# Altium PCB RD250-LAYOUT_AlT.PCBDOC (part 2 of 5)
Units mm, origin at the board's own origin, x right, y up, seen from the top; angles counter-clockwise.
Board outline 318.5 x 135 mm, 6 copper layers (TOP, Mid-Layer 1, Mid-Layer 2, Mid-Layer 3, Mid-Layer 4, BOTTOM), stack 1.422 mm thick; 550 components, 251 nets, 1350 pads, 626 vias.
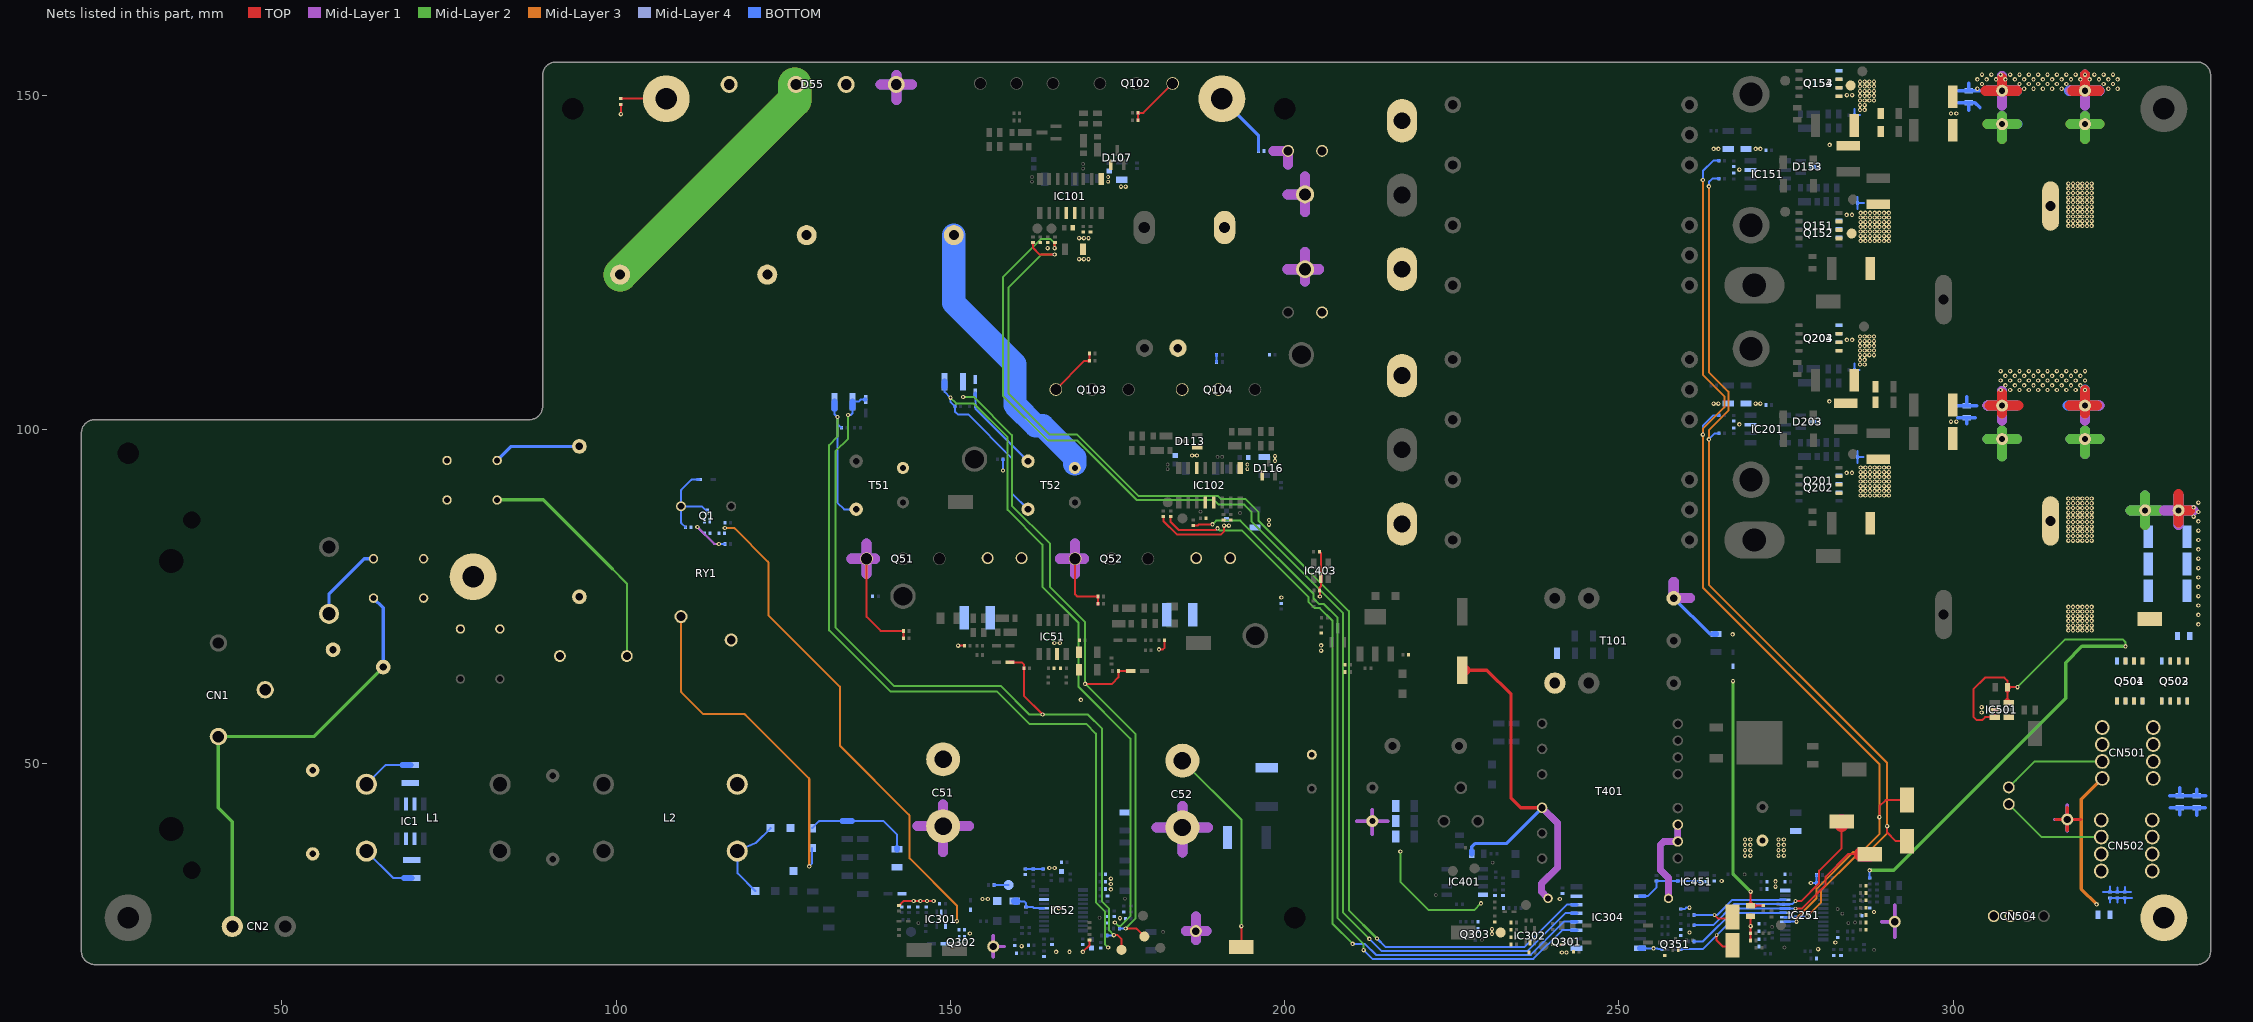
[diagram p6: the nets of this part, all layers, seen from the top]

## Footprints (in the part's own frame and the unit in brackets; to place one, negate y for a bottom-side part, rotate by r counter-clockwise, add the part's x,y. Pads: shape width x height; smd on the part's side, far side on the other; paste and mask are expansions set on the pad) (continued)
Local_TAM0545 [mm] "KC00080BKP"
  round 2.5 hole 1.4 paste-2.5 mask+0: 1(-13.5,-17.7) 3(-4.5,-17.7) 4(4.5,-17.7) 6(13.5,-17.7) 7(13.5,17.7) 8(9,17.7) 9(4.5,17.7) 10(-4.5,17.7) 11(-9,17.7) 12(-13.5,17.7)
  silkscreen extent -18.7,-20.7 18.7,20.7
Local_TAM-PQ20-36-5 [mil] "KC00080BKP"
  round 62 / inner round 52 / far side round 62 hole 42 paste-62 mask+0: 1(-397.64,-399.61) 2(-248.03,-399.61) 3(-98.43,-399.61) 4(98.43,-399.61) 5(248.03,-399.61) 6(397.64,-399.61) 7(395.28,399.61) 8(296.85,399.61) 9(198.43,399.61) 10(100,399.61) 11(-100,399.61) 12(-198.43,399.61) 13(-296.85,399.61) 14(-395.28,399.61)
  silkscreen extent -500,-539 500,539
Local_TH350-P550 [mm] "KC00080BKP"
  round 5.5 hole 3.5 paste-5.5 mask+0: 1(0,0)
  silkscreen extent -3,-3 3,3
Local_TMSD-Y3001 [mm] "KC00080BKP"
  oval 5x3.2 / inner round 0 / far side oval 5x3.2 hole 1.7 slot 3.5 at 0 deg paste-5 mask+0: 1(0,-6) 2(0,6)
Local_TO-220-2L-A [mil] "KC00080BKP"
  round 70 / inner round 0 / far side round 70 hole 51.18 paste-70 mask+0: A(0,0) C(200,0)
  silkscreen extent -109,-121 309,72
Local_TO-220SIS-02-A [mm] "KC00080BKP"
  round 1.9 hole 1.3 paste-2 mask+0: D(0,-5) G(-2.54,0) S(2.54,0)
  silkscreen extent -5,-3.84 5,2.92
Local_Y5JA-330JPTL3_5-A [mm] "KC00080BKP"
  round 1.778 / inner round 0 / far side round 1.778 hole 1.2 paste-1.778 mask+0: 1(-5,0) 2(5,0)
  silkscreen extent -9.7,-5.35 9.7,5.35
LocalI9K0A8 [mm] "KC00080BKP"
  rect 0.825x1.795 smd paste-1.795 mask+0: 1(-4.583,-4.72) 8(4.583,-4.72) 9(4.583,4.72) 16(-4.583,4.72)
  rect 0.55x1.795 smd paste-1.795 mask+0: 2(-3.175,-4.72) 3(-1.905,-4.72) 4(-0.635,-4.72) 5(0.635,-4.72) 6(1.905,-4.72) 7(3.175,-4.72) 10(3.175,4.72) 11(1.905,4.72) 12(0.635,4.72) 13(-0.635,4.72) 14(-1.905,4.72) 15(-3.175,4.72)
  silkscreen extent -5.3,-5.92 5.25,3.32
MM00340AKP [mm] "KC00080BKP"
  rect 0.5x0.9 smd paste-0.9 mask+0: D(0,0.65)
  rect 0.4x0.9 smd paste-0.9 mask+0: G(-0.4,-0.65) S(0.4,-0.65)
  silkscreen extent -0.65,0.1 0.65,0.45
MM00340BKP [mm] "KC00080BKP"
  rect 0.5x0.9 smd paste-0.9 mask+0: D(0,-0.65)
  rect 0.4x0.9 smd paste-0.9 mask+0: G(0.4,0.65) S(-0.4,0.65)
  silkscreen extent -0.65,-0.45 0.65,-0.1
MM00730AKP [mm] "KC00080BKP"
  rect 0.4x0.95 smd paste-0.95 mask+0: 1(-0.65,-0.975) 2(0,-0.975) 3(0.65,-0.975) 4(0.65,0.975) 5(-0.65,0.975)
MM00730BKP [mm] "KC00080BKP"
  rect 0.4x0.95 smd paste-0.95 mask+0: 1(-0.65,-0.975) 2(0,-0.975) 3(0.65,-0.975) 4(0.65,0.975) 5(-0.65,0.975)
MM01320AKP [mm] "KC00080BKP"
  rect 1x2.25 smd paste-2.25 mask+0: 1(-2.3,-2.775) 2(0,-2.775) 3(2.3,-2.775)
  rect 3.2x2.25 smd paste-3.2 mask+0: 4(0,2.775)
  silkscreen extent -3.35,-1.85 3.35,1.85
MMK01670AKP [mm] "KC00080BKP"
  rect 1.212x1.2 smd paste-1.212 mask+0: A(-1.494,0) C(1.494,0)
  silkscreen extent -2.4,-0.9 2.9,0.9
MMK01670BKP [mm] "KC00080BKP"
  rect 1.212x1.2 smd paste-1.212 mask+0: A(1.494,0) C(-1.494,0)
  silkscreen extent -2.9,-0.9 2.4,0.9
NTC320 [mm] "KC00080BKP"
  round 0 hole 3.2 unplated paste-3.5 mask+0: ""(0,0)
R8100A [mm] "KC00080BKP"
  rect 1.405x3.4 smd paste-3.4 mask+0: 1(-2.903,0) 2(2.902,0)
R9100A [mm] "KC00080BKP"
  rect 1.405x3.4 smd paste-3.4 mask+0: 1(-2.903,0) 2(2.902,0)
RDP10020ATP#1 [mm] "KC00080BKP"
  round 1.9 / inner round 0 / far side round 1.9 hole 1.65 paste-1.9 mask+0: D(5.44,0) G(0,0) S(10.88,0)
  silkscreen extent -3.15,-2.9 14.05,3.35
RDP10020ATP#2 [mm] "KC00080BKP"
  round 1.9 / inner round 0 / far side round 1.9 hole 1.65 paste-1.9 mask+0: D(5.44,0) G(0,0)
  round 1.9 / inner round 2 / far side round 1.9 hole 1.65 paste-1.9 mask+0: S(10.88,0)
  silkscreen extent -3.15,-2.9 14.05,3.35
SIK00180ATP_RD244-A [mm] "KC00080BKP"
  round 1.4 / inner round 0 / far side round 1.4 hole 0.9 paste-1.4 mask+0: 1(-5.25,0) 2(12.75,0)
  silkscreen extent -4.8,-3 12.3,3
SOT-23-6_KA [mm] "KC00080BKP"
  rect 0.825x1.56 smd paste-1.56 mask+0: 1(-1.087,-1.075) 3(1.088,-1.075) 4(1.088,1.075) 6(-1.087,1.075)
  rect 0.55x1.56 smd paste-1.56 mask+0: 2(0,-1.075) 5(0,1.075)
T3.2_7.0 [mm] "KC00080BKP"
  round 7 / inner round 0 / far side round 7 hole 3.2 paste-7.1 mask+0: ""(0,0)
US2H_A [mm] "KC00080BKP"
  rect 0.8x1.1 smd paste-1.1 mask+0: A(1.25,0)
  rect 2x1.1 smd paste-2 mask+0: C(-0.65,0)
  silkscreen extent -1.9,-0.9 1.9,0.9
US2H_B [mm] "KC00080BKP"
  rect 0.8x1.1 smd paste-1.1 mask+0: A(-1.25,0)
  rect 2x1.1 smd paste-2 mask+0: C(0.65,0)
  silkscreen extent -1.95,-0.85 2.01,0.85
UTOS12 [mm] "KC00080BKP"

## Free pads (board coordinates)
  round 0.55 / inner round 0 / far side round 0.55 hole 0.3 paste-0.55 mask+0: ""(145.2,26.2) ""(162.2,137.1) ""(162.2,137.8) ""(169.85,139.05) ""(169.85,139.75) ""(172.3,27) ""(173.6,137.1) ""(173.6,137.8) ""(176.1,29.85) ""(181.8,24.9) ""(182.5,94.1) ""(182.5,94.8) ""(187.4,87.75) ""(189.95,95.95) ""(190.65,95.95) ""(193.3,87.55) ""(194.4,94.1) ""(194.4,94.8) ""(222.6,30.4) ""(229.5,23.7) ""(231.1,35.25) ""(264.3,27.4) ""(264.6,24.4) ""(268.8,33.5) ""(272.9,25.65) ""(274.75,22.55) ""(276.4,28.35) ""(276.4,29.5) ""(282.7,28.3) ""(283.4,27.6) ""(284.3,26.2) ""(285.3,26.3) ""(288.15,22.2)
  round 0 hole 1 slot 13.5 at 0 deg unplated paste-13.5 mask+0: ""(168,134.95) ""(188.8,91.7)

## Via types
v1: diameter 0.65, hole 0.3, TOP to BOTTOM, 626 vias

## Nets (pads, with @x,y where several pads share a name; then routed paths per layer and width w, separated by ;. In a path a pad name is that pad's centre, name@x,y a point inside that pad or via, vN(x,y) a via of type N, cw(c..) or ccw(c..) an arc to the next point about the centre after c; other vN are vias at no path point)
ACIN: C301.2 D51.C D52.C R301.1 | length 16.2
  BOTTOM w0.3: D51.C@129.3,40.394 130.324,41.418 cw(c130.466,41.277) 130.466,41.477 R301.1@133.888,41.477 ; R301.1@135.278,41.477 139.897,41.477 cw(c139.897,41.277) 140.038,41.419 141.941,39.516 cw(c141.8,39.374) 142,39.374 C301.2@142,37.433
  BOTTOM w0.92: R301.1@133.888,41.477 R301.1@134.583,41.477 R301.1@135.278,41.477 ; C301.2@142,37.25 C301.2@142,37.433
CONN002: C119.1 C120.1 CN101.1 CN104.1 D113.A IC102.14 Q103.S Q104.D R121.1 | length 7.9
  TOP w0.3: Q103.S@165.72,106 170.02,110.3 C120.1@170.597,110.3 ; C120.1@170.775,110.478 R121.1@170.775,111.222
  TOP w0.45: C120.1@170.597,110.3 C120.1@170.775,110.3 C120.1@170.775,110.478 ; R121.1@170.775,111.222 R121.1@170.775,111.4
  other v1: 186.15,96.15 186.85,96.15
CONN003: CN103.1 CN106.1 D108.A D109.C L101.2
CONN004: C501.2 C502.2 C503.2 C504.2 C505.2 C506.2 C507.2 C508.2 C509.2 DP503.1 IC501.3 IC501.6 L151.F L201.F Q501.1 Q501.2 Q501.3 Q502.1 Q502.2 Q502.3 Q503.1 Q503.2 Q503.3 Q504.1 Q504.2 Q504.3 R162.2 R163.2 R212.2 R213.2 R287.2 R501.2 R502.2 R503.2 | length 222.9
  TOP w0.3: IC501.3@305.808,57.012 304.762,57.012 304.3,56.55 303.5,56.55 303,57.05 303,61.15 304.75,62.9 307.65,62.9 308.1,62.45 C509.2@308.1,61.81 ; IC501.6@308.1,59.469 C509.2@308.1,61.031 ; C509.2@308.21,61.5 v1(309.6,61.5)
  TOP w0.8: C509.2@308.1,61.031 C509.2@308.1,61.5 ; C509.2@308.1,61.81 C509.2@308.1,61.5 ; C509.2@308.21,61.5 C509.2@308.1,61.5
  TOP w0.825: IC501.3@305.808,57.012 IC501.3@306.175,57.012 ; IC501.6@308.1,59.187 IC501.6@308.1,59.469
  Mid-Layer 2 w0.3: v1(309.6,61.5) 316.75,68.65 325.35,68.65 325.75,68.25 v1(325.75,67.6)
  Mid-Layer 2 w0.5: v1(287.5,34.1) 291.1,34.1 316.8,59.8 316.8,65.15 319.25,67.6 v1(325.75,67.6)
  Mid-Layer 2 w1.5: 305.1,98.6 C504.2@307.3,98.6 ; 305.1,145.7 C501.2@307.3,145.7 ; 307.3,96 C504.2@307.3,98.6 ; 307.3,99.85 C504.2@307.3,98.6 ; 307.3,143.5 C501.2@307.3,145.7 ; 307.3,146.95 C501.2@307.3,145.7 ; 309.5,98.6 C504.2@307.3,98.6 ; 309.5,145.7 C501.2@307.3,145.7 ; 317.5,98.6 C505.2@319.7,98.6 ; 317.5,145.7 C502.2@319.7,145.7 ; 319.7,96.4 C505.2@319.7,98.6 ; 319.7,99.85 C505.2@319.7,98.6 ; 319.7,143.5 C502.2@319.7,145.7 ; 319.7,146.95 C502.2@319.7,145.7 ; 321.9,98.6 C505.2@319.7,98.6 ; 321.9,145.7 C502.2@319.7,145.7 ; 326.5,87.95 C503.2@328.7,87.95 ; 328.7,85.75 C503.2@328.7,87.95 ; 328.7,90.15 C503.2@328.7,87.95 ; 330.9,87.95 C503.2@328.7,87.95
  Mid-Layer 3 w1.5: 305.1,98.6 C504.2@307.3,98.6 ; 305.1,145.7 C501.2@307.3,145.7 ; 307.3,96.05 C504.2@307.3,98.6 ; 307.3,99.85 C504.2@307.3,98.6 ; 307.3,143.5 C501.2@307.3,145.7 ; 307.3,146.95 C501.2@307.3,145.7 ; 309.5,98.6 C504.2@307.3,98.6 ; 309.5,145.7 C501.2@307.3,145.7 ; 317.5,98.6 C505.2@319.7,98.6 ; 317.5,145.7 C502.2@319.7,145.7 ; 319.7,96.4 C505.2@319.7,98.6 ; 319.7,99.85 C505.2@319.7,98.6 ; 319.7,143.5 C502.2@319.7,145.7 ; 319.7,146.95 C502.2@319.7,145.7 ; 321.9,98.6 C505.2@319.7,98.6 ; 321.9,145.7 C502.2@319.7,145.7 ; 326.5,87.95 C503.2@328.7,87.95 ; 328.7,85.75 C503.2@328.7,87.95 ; 328.7,90.15 C503.2@328.7,87.95 ; 330.9,87.95 C503.2@328.7,87.95
  BOTTOM w0.3: R287.2@287.5,33.103 v1(287.5,34.1)
  BOTTOM w0.45: R287.2@287.5,32.925 R287.2@287.5,33.103
  BOTTOM w0.5: 300.65,101.8 C506.2@302,101.8 ; 300.75,148.9 C507.2@302.3,148.9 ; 302,100.9 C506.2@302,101.8 ; 302.3,147.75 C507.2@302.3,148.9 ; 303.3,101.8 C506.2@302,101.8 ; 304,148.15 303.25,148.9 C507.2@302.3,148.9
  BOTTOM w1.5: 305.1,98.6 C504.2@307.3,98.6 ; 305.25,145.7 C501.2@307.3,145.7 ; 307.3,96.05 C504.2@307.3,98.6 ; 307.3,99.85 C504.2@307.3,98.6 ; 307.3,143.65 C501.2@307.3,145.7 ; 307.3,146.95 C501.2@307.3,145.7 ; 309.5,98.6 C504.2@307.3,98.6 ; 309.6,145.7 C501.2@307.3,145.7 ; 317.5,98.6 C505.2@319.7,98.6 ; 317.9,145.7 C502.2@319.7,145.7 ; 319.7,96.4 C505.2@319.7,98.6 ; 319.7,99.8 C505.2@319.7,98.6 ; 319.7,144 C502.2@319.7,145.7 ; 319.7,146.95 C502.2@319.7,145.7 ; 321.7,145.7 C502.2@319.7,145.7 ; 321.9,98.6 C505.2@319.7,98.6 ; 326.5,87.95 C503.2@328.7,87.95 ; 328.7,86.25 C503.2@328.7,87.95 ; 328.7,90.15 C503.2@328.7,87.95 ; 330.9,87.95 C503.2@328.7,87.95
  other v1: 317.2,70 317.9,70 318.6,70 319.3,70 320,70 320.7,70 317.2,70.7 317.9,70.7 318.6,70.7 319.3,70.7 320,70.7 320.7,70.7 317.2,71.4 317.9,71.4 318.6,71.4 319.3,71.4 320,71.4 320.7,71.4 317.2,72.1 317.9,72.1 318.6,72.1 319.3,72.1 320,72.1 320.7,72.1 317.2,72.8 317.9,72.8 318.6,72.8 319.3,72.8 320,72.8 320.7,72.8 317.2,73.5 317.9,73.5 318.6,73.5 319.3,73.5 320,73.5 320.7,73.5 317.2,83.4 317.9,83.4 318.6,83.4 319.3,83.4 320,83.4 320.7,83.4 317.2,84.1 317.9,84.1 318.6,84.1 319.3,84.1 320,84.1 320.7,84.1 317.2,84.8 317.9,84.8 318.6,84.8 319.3,84.8 320,84.8 320.7,84.8 317.2,85.5 317.9,85.5 318.6,85.5 319.3,85.5 320,85.5 320.7,85.5 317.2,86.2 317.9,86.2 318.6,86.2 319.3,86.2 320,86.2 320.7,86.2 317.2,86.9 317.9,86.9 318.6,86.9 319.3,86.9 320,86.9 320.7,86.9 317.2,87.6 317.9,87.6 318.6,87.6 319.3,87.6 320,87.6 320.7,87.6 317.2,88.3 317.9,88.3 318.6,88.3 319.3,88.3 320,88.3 320.7,88.3 317.2,89 317.9,89 318.6,89 319.3,89 320,89 320.7,89 317.2,89.7 317.9,89.7 318.6,89.7 319.3,89.7 320,89.7 320.7,89.7 299.65,101.2 300.45,101.2 317.2,130.5 317.9,130.5 318.6,130.5 319.3,130.5 320,130.5 320.7,130.5 317.2,131.2 317.9,131.2 318.6,131.2 319.3,131.2 320,131.2 320.7,131.2 317.2,131.9 317.9,131.9 318.6,131.9 319.3,131.9 320,131.9 320.7,131.9 317.2,132.6 317.9,132.6 318.6,132.6 319.3,132.6 320,132.6 320.7,132.6 317.2,133.3 317.9,133.3 318.6,133.3 319.3,133.3 320,133.3 320.7,133.3 317.2,134 317.9,134 318.6,134 319.3,134 320,134 320.7,134 317.2,134.7 317.9,134.7 318.6,134.7 319.3,134.7 320,134.7 320.7,134.7 317.2,135.4 317.9,135.4 318.6,135.4 319.3,135.4 320,135.4 320.7,135.4 317.2,136.1 317.9,136.1 318.6,136.1 319.3,136.1 320,136.1 320.7,136.1 317.2,136.8 317.9,136.8 318.6,136.8 319.3,136.8 320,136.8 320.7,136.8 299.65,147.3 300.45,147.3
CS: D251.C R282.2 R284.2 | length 36.6
  TOP w0.3: R284.2@269.7,29.049 v1(269.7,30.9) ; R284.2@270.116,28.8 R282.2@271.425,28.8
  TOP w0.4: R282.2@271.425,28.8 R282.2@271.6,28.8
  TOP w0.83: R284.2@269.7,29.049 R284.2@269.7,28.8 R284.2@270.116,28.8
  Mid-Layer 2 w0.5: v1(267.05,62.4) 267.05,33.55 v1(269.7,30.9)
CSA: D58.C D62.C DP52.1 R52.2 R59.1 R68.1 | length 129.7
  TOP w0.3: D62.C@159.33,65.2 160.675,65.2 160.975,64.9 R59.1@160.975,64.478 ; R59.1@160.975,64.122 160.975,60.225 v1(163.8,57.4) ; v1(174.45,24.4) 175,24.4 175.6,23.8 DP52.1@175.6,22.2
  TOP w0.45: R59.1@160.975,64.122 R59.1@160.975,64.3 R59.1@160.975,64.478
  TOP w0.55: D62.C@158.925,65.2 D62.C@159.33,65.2
  Mid-Layer 2 w0.3: v1(134.7,102.2) 134.7,98.65 132.8,96.75 132.8,70.45 141.55,61.7 157.5,61.7 161.8,57.4 v1(163.8,57.4) 170.55,57.4 172.7,55.25 172.7,29.4 173.75,28.35 173.75,25.1 v1(174.45,24.4)
  BOTTOM w0.3: v1(134.7,102.2) 135.073,102.2 135.373,102.5 R52.2@135.373,103.216 ; R52.2@135.373,104.2 136.3,104.2 136.625,104.525 D58.C@137.113,104.525 ; R68.1@173.577,24.35 v1@174.45,24.35
  BOTTOM w0.45: R68.1@173.425,24.35 R68.1@173.577,24.35
  BOTTOM w0.55: D58.C@137.113,104.525 D58.C@137.31,104.525
  BOTTOM w0.895: R52.2@135.373,103.216 R52.2@135.373,104.2
CSB: D63.C D67.C DP54.1 R60.2 R67.1 R69.1 | length 104.1
  TOP w0.3: v1(170.15,62) 174.175,62 175.125,62.95 R67.1@175.125,63.722 ; R67.1@175.303,63.9 D67.C@176.373,63.9 ; v1(176.2,25.4) 177.717,25.4 cw(c177.717,25.2) 177.859,25.341 DP54.1@179,24.2
  TOP w0.45: R67.1@175.125,63.722 R67.1@175.125,63.9 R67.1@175.303,63.9
  TOP w0.55: D67.C@176.373,63.9 D67.C@176.975,63.9
  Mid-Layer 2 w0.3: v1(151.9,104.9) 153.5,104.9 159.2,99.2 159.2,88.65 164.9,82.95 164.9,76.45 170.15,71.2 v1(170.15,62) 177.7,54.45 177.7,26.9 v1(176.2,25.4)
  BOTTOM w0.3: R69.1@175.378,25.4 v1(176.2,25.4)
  BOTTOM w0.45: R69.1@175.275,25.4 R69.1@175.378,25.4
FG1: C2.1 C3.1 C4.1 C5.1 C7.1 C8.1 cam7. CN1.2
FG2: C512.1 C513.2 cam5. R505.1 R506.1 | length 5.5
  BOTTOM w0.3: 323.45,29.25 C513.2@323.45,29.975 R505.1@324.55,29.975 ; 324.55,29.25 R505.1@324.55,29.967 R505.1@324.55,29.975 ; 325.65,29.2 R506.1@325.65,29.975 ; 326.75,29.975 R506.1@325.65,29.975 ; R505.1@324.55,29.975 R506.1@325.65,29.975
HS1_1: cam8. R422.2 | length 6.9
  TOP w0.3: R422.2@100.878,149.525 cam8.@107.6,149.525
  TOP w0.45: R422.2@100.7,149.525 R422.2@100.878,149.525
HS1_2: cam2. R423.2 | length 10.1
  BOTTOM w0.5: cam2.@190.6,149.5 196.075,144.025 R423.2@196.075,141.7
LGND: C151.1 C152.1 C153.1 C156.1 C157.1 C158.1 C159.1 C201.1 C202.1 C203.1 C206.1 C207.1 C208.1 C209.1 C251.1 C252.1 C253.1 C254.1 C255.1 C351.1 C414.2 C451.1 C452.1 C453.1 C501.1 C502.1 C503.1 C504.1 C505.1 C506.1 C507.1 C508.1 C510.1 C511.1 C513.1 CN502.1 CN502.2 CN502.3 CN502.4 CN502.5 CN502.6 CN502.7 CN502.8 CN503.2 CN504.3 CN504.4 D153.C D203.C DP153.1 DP156.1 DP257.1 DP501.1 IC151.3 IC201.3 IC251.24 IC304.2 IC304.8 IC451.2 IC501.2 Q151.1 Q151.2 Q151.3 Q152.1 Q152.2 Q152.3 Q153.1 Q153.2 Q153.3 Q154.1 Q154.2 Q154.3 Q201.1 Q201.2 Q201.3 Q202.1 Q202.2 Q202.3 Q203.1 Q203.2 Q203.3 Q204.1 Q204.2 Q204.3 Q351.S R154.1 R155.1 R158.1 R159.1 R160.1 R161.1 R204.1 R205.1 R208.1 R209.1 R210.1 R211.1 R251.1 R252.1 R253.1 R254.1 R255.1 R256.1 R257.1 R258.1 R259.1 R262.1 R264.1 R267.1 R269.1 R271.1 R273.1 R275.1 R276.1 R281.1 R283.1 R284.1 R285.1 R291.1 R352.1 R356.1 R359.1 R362.1 R365.1 R451.1 R501.1 R502.1 R503.1 R505.2 R506.2 T101.3 T401.8 T401.9 | length 311.2
  TOP w0.3: R275.1@269.7,23.769 R271.1@269.7,24.531 ; R271.1@269.7,24.869 v1(269.7,25.75) R284.1@269.7,27.139
  TOP w0.4: R275.1@269.7,23.6 R275.1@269.7,23.769 ; R271.1@269.7,24.531 R271.1@269.7,24.869
  TOP w0.5: 315.3,41.7 DP501.1@317.05,41.7 ; 317.05,40.1 DP501.1@317.05,41.7 ; 317.05,43.45 DP501.1@317.05,41.7 ; 319.05,41.7 DP501.1@317.05,41.7
  TOP w0.83: R284.1@269.7,27.139 R284.1@269.7,27.2
  TOP w1.5: 304.85,150.7 C501.1@307.3,150.7 ; 305.45,103.6 C504.1@307.3,103.6 ; 307.3,102.45 C504.1@307.3,103.6 ; 307.3,105.4 C504.1@307.3,103.6 ; 307.3,152.6 C501.1@307.3,150.7 ; 309.55,150.7 C501.1@307.3,150.7 ; 309.75,103.6 C504.1@307.3,103.6 ; 317.35,103.6 C505.1@319.7,103.6 ; 317.85,150.7 C502.1@319.7,150.7 ; 319.7,102.45 C505.1@319.7,103.6 ; v1(319.7,105.95) C505.1@319.7,103.6 ; v1(319.7,153.1) C502.1@319.7,150.7 ; 321.5,103.6 C505.1@319.7,103.6 ; 321.8,150.7 C502.1@319.7,150.7 ; 333.7,86.1 C503.1@333.7,87.95 ; 333.7,90.35 C503.1@333.7,87.95 ; 335.4,87.95 C503.1@333.7,87.95
  Mid-Layer 1 w0.5: 289.3,26.4 DP257.1@291.25,26.4 ; 291.25,24.05 DP257.1@291.25,26.4 ; 291.25,28.85 DP257.1@291.25,26.4 ; 315.15,41.7 DP501.1@317.05,41.7 ; 317.05,40 DP501.1@317.05,41.7 ; 317.05,43.85 DP501.1@317.05,41.7 ; 318.9,41.7 DP501.1@317.05,41.7
  Mid-Layer 1 w1: C414.2@257.4,29.9 257.4,32.95 256.15,34.2 256.15,37.85 256.71,38.41 T401.8@258.8,38.41 T401.9@258.8,40.91
  Mid-Layer 1 w1.5: 258.19,77.2 T101.3@258.19,74.8 260.59,74.8 ; 305.1,103.6 C504.1@307.3,103.6 ; 305.1,150.7 C501.1@307.3,150.7 ; 307.3,101.4 C504.1@307.3,103.6 ; v1@307.3,105.8 C504.1@307.3,103.6 ; 307.3,148.5 C501.1@307.3,150.7 ; v1@307.3,152.9 C501.1@307.3,150.7 ; 309.5,103.6 C504.1@307.3,103.6 ; 309.5,150.7 C501.1@307.3,150.7 ; 317.5,103.6 C505.1@319.7,103.6 ; 317.5,150.7 C502.1@319.7,150.7 ; 319.7,101.4 C505.1@319.7,103.6 ; v1@319.7,105.8 C505.1@319.7,103.6 ; 319.7,148.5 C502.1@319.7,150.7 ; v1@319.7,152.9 C502.1@319.7,150.7 ; 321.9,103.6 C505.1@319.7,103.6 ; 321.9,150.7 C502.1@319.7,150.7 ; 331.5,87.95 C503.1@333.7,87.95 ; 333.7,85.75 C503.1@333.7,87.95 ; 333.7,90.15 C503.1@333.7,87.95 ; 335.9,87.95 C503.1@333.7,87.95
  Mid-Layer 2 w0.3: CN503.2@308.3,44 313.23,39.07 CN502.2@322.14,39.07
  Mid-Layer 4 w0.5: 289.3,26.4 DP257.1@291.25,26.4 ; 291.25,24.05 DP257.1@291.25,26.4 ; 291.25,28.85 DP257.1@291.25,26.4 ; 315.15,41.7 DP501.1@317.05,41.7 ; 317.05,40 DP501.1@317.05,41.7 ; 317.05,43.85 DP501.1@317.05,41.7 ; 318.9,41.7 DP501.1@317.05,41.7
  Mid-Layer 4 w1: C414.2@257.4,29.9 257.4,32.95 256.15,34.2 256.15,37.85 256.71,38.41 T401.8@258.8,38.41 T401.9@258.8,40.91
  Mid-Layer 4 w1.5: 258.19,77.2 T101.3@258.19,74.8 260.59,74.8 ; 305.1,103.6 C504.1@307.3,103.6 ; 305.1,150.7 C501.1@307.3,150.7 ; 307.3,101.4 C504.1@307.3,103.6 ; v1@307.3,105.8 C504.1@307.3,103.6 ; 307.3,148.5 C501.1@307.3,150.7 ; v1@307.3,152.9 C501.1@307.3,150.7 ; 309.5,103.6 C504.1@307.3,103.6 ; 309.5,150.7 C501.1@307.3,150.7 ; 317.5,103.6 C505.1@319.7,103.6 ; 317.5,150.7 C502.1@319.7,150.7 ; 319.7,101.4 C505.1@319.7,103.6 ; v1@319.7,105.8 C505.1@319.7,103.6 ; 319.7,148.5 C502.1@319.7,150.7 ; v1@319.7,152.9 C502.1@319.7,150.7 ; 321.9,103.6 C505.1@319.7,103.6 ; 321.9,150.7 C502.1@319.7,150.7 ; 331.5,87.95 C503.1@333.7,87.95 ; 333.7,85.75 C503.1@333.7,87.95 ; 333.7,90.15 C503.1@333.7,87.95 ; 335.9,87.95 C503.1@333.7,87.95
  BOTTOM w0.3: IC304.8@253.718,22.417 v1(255.15,22.417) 255.733,22.417 255.85,22.3 R365.1@256.272,22.3 ; IC304.2@253.885,30.225 254.325,30.225 255.6,31.5 C351.1@255.6,32.347 ; C351.1@255.778,32.475 C453.1@258.622,32.475 ; C453.1@258.978,32.475 IC451.2@261.926,32.475 ; R356.1@259.29,28.325 259.875,28.325 260.05,28.5 v1(260.55,28.5) ; v1(278.7,32.2) C254.1@279.5,32.2 ; C254.1@279.575,32.378 R273.1@279.575,33.222 ; 285.225,107.9 R208.1@285.225,108.95 ; 285.225,109.9 R208.1@285.225,108.95 ; 285.225,146.05 R158.1@285.225,147.05 ; 285.225,148 R158.1@285.225,147.05 ; 285.675,95 R204.1@285.675,95.9 ; 285.675,96.85 R204.1@285.675,95.9 ; 285.675,133.05 R154.1@285.675,133.9 ; 285.675,134.8 R154.1@285.675,133.9 ; 286,108.95 R208.1@285.225,108.95 ; 286.05,147.05 R158.1@285.225,147.05 ; 286.55,95.9 R204.1@285.675,95.9 ; 286.65,133.9 R154.1@285.675,133.9 ; 322.4,30.825 C513.1@323.45,30.825 ; 323.45,31.65 C513.1@323.45,30.825 ; 324.55,31.55 R505.2@324.55,30.825 ; 325.65,31.6 R506.2@325.65,30.825 ; 326.6,30.825 R506.2@325.65,30.825 ; C513.1@323.45,30.825 R505.2@324.55,30.825 ; R505.2@324.55,30.825 R506.2@325.65,30.825
  BOTTOM w0.4: IC451.2@261.926,32.475 IC451.2@262.675,32.475
  BOTTOM w0.45: C351.1@255.6,32.347 C351.1@255.6,32.475 C351.1@255.778,32.475 ; R365.1@256.272,22.3 R365.1@256.45,22.3 ; C453.1@258.622,32.475 C453.1@258.8,32.475 C453.1@258.978,32.475 ; R356.1@259.25,28.325 R356.1@259.29,28.325 ; C254.1@279.5,32.2 C254.1@279.575,32.2 C254.1@279.575,32.378 ; R273.1@279.575,33.222 R273.1@279.575,33.4
  BOTTOM w0.5: T101.3@258.19,74.8 263.54,69.45 R251.1@264.11,69.45 ; 300.2,103.6 C506.1@302,103.6 ; 300.75,150.7 C507.1@302.3,150.7 ; 302,104.95 C506.1@302,103.6 ; 302.3,151.85 C507.1@302.3,150.7 ; 303.55,103.6 C506.1@302,103.6 ; 303.95,150.7 C507.1@302.3,150.7 ; 315.3,41.7 DP501.1@317.05,41.7 ; 317.05,40.15 DP501.1@317.05,41.7 ; 317.05,43.45 DP501.1@317.05,41.7 ; 318.85,41.7 DP501.1@317.05,41.7 ; 332.45,43.45 C510.1@333.9,43.45 ; 333.9,42.4 C510.1@333.9,43.45 ; 336.4,42.35 C511.1@336.4,43.45 ; 337.7,43.45 C511.1@336.4,43.45 ; C510.1@333.9,43.45 C511.1@336.4,43.45
  BOTTOM w0.55: IC304.2@253.12,30.225 IC304.2@253.885,30.225
  BOTTOM w0.825: IC304.8@253.12,22.417 IC304.8@253.718,22.417
  BOTTOM w0.92: R251.1@264.11,69.45 R251.1@264.5,69.45
  BOTTOM w1.5: 305.1,103.6 C504.1@307.3,103.6 ; 305.35,150.7 C501.1@307.3,150.7 ; 307.3,102.45 C504.1@307.3,103.6 ; 307.3,105.3 C504.1@307.3,103.6 ; 307.3,149.45 C501.1@307.3,150.7 ; 307.3,152.65 C501.1@307.3,150.7 ; 309.1,150.7 C501.1@307.3,150.7 ; 309.35,103.6 C504.1@307.3,103.6 ; 317.1,103.6 C505.1@319.7,103.6 ; 317.3,150.7 C502.1@319.7,150.7 ; 319.7,102.45 C505.1@319.7,103.6 ; v1@319.7,106.05 v1(319.7,105.95) C505.1@319.7,103.6 ; 319.7,149.45 C502.1@319.7,150.7 ; v1(319.7,153.1) C502.1@319.7,150.7 ; 320.9,103.6 C505.1@319.7,103.6 ; 321.75,150.7 C502.1@319.7,150.7
  other v1: 279.8,22.3 282.35,23.3 260.55,24.8 288.15,27.85 273.4,31.65 273.4,32.45 265.35,32.5 268.85,36.3 269.65,36.3 273.85,36.3 274.65,36.3 268.85,37.1 269.65,37.1 273.85,37.1 274.65,37.1 268.85,37.9 269.65,37.9 273.85,37.9 274.65,37.9 268.85,38.7 269.65,38.7 273.85,38.7 274.65,38.7 304.25,57.7 304.25,58.5 267,69.4 336.65,70.9 336.65,72.3 336.65,73.7 336.65,75.1 336.65,76.5 336.65,77.9 336.65,79.3 336.65,80.7 336.65,82.1 336.65,83.5 336.65,84.9 336.65,86.3 335.95,87 336.65,87.7 335.95,88.4 336.65,89.1 286.15,90.15 286.85,90.15 287.55,90.15 288.25,90.15 288.95,90.15 289.65,90.15 290.35,90.15 286.15,90.85 286.85,90.85 287.55,90.85 288.25,90.85 288.95,90.85 289.65,90.85 290.35,90.85 286.15,91.55 286.85,91.55 287.55,91.55 288.25,91.55 288.95,91.55 289.65,91.55 290.35,91.55 286.15,92.25 286.85,92.25 287.55,92.25 288.25,92.25 288.95,92.25 289.65,92.25 290.35,92.25 286.15,92.95 286.85,92.95 287.55,92.95 288.25,92.95 288.95,92.95 289.65,92.95 290.35,92.95 284.05,93.55 284.85,93.55 286.15,93.65 286.85,93.65 287.55,93.65 288.25,93.65 288.95,93.65 289.65,93.65 290.35,93.65 286.15,94.35 286.85,94.35 287.55,94.35 288.25,94.35 288.95,94.35 289.65,94.35 290.35,94.35 268,100.8 264.15,103.9 264.85,103.9 270.45,103.9 271.15,103.9 281.45,104.25 307.1,105.95 308.5,105.95 309.9,105.95 311.3,105.95 312.7,105.95 314.1,105.95 315.5,105.95 316.9,105.95 318.3,105.95 307.8,106.65 309.2,106.65 310.6,106.65 312,106.65 313.4,106.65 314.8,106.65 316.2,106.65 317.6,106.65 319,106.65 307.1,107.35 308.5,107.35 309.9,107.35 311.3,107.35 312.7,107.35 314.1,107.35 315.5,107.35 316.9,107.35 318.3,107.35 319.7,107.35 307.8,108.05 309.2,108.05 310.6,108.05 312,108.05 313.4,108.05 314.8,108.05 316.2,108.05 317.6,108.05 319,108.05 307.1,108.75 308.5,108.75 309.9,108.75 311.3,108.75 312.7,108.75 314.1,108.75 315.5,108.75 316.9,108.75 318.3,108.75 319.7,108.75 286.05,109.75 286.75,109.75 286.05,110.45 286.75,110.45 286.05,111.15 286.75,111.15 287.45,111.15 288.15,111.15 286.05,111.85 286.75,111.85 287.45,111.85 288.15,111.85 286.05,112.55 286.75,112.55 287.45,112.55 288.15,112.55 286.05,113.25 286.75,113.25 287.45,113.25 288.15,113.25 284.075,113.45 284.875,113.45 286.05,113.95 286.75,113.95 287.45,113.95 288.15,113.95 286.15,128.25 286.85,128.25 287.55,128.25 288.25,128.25 288.95,128.25 289.65,128.25 290.35,128.25 286.15,128.95 286.85,128.95 287.55,128.95 288.25,128.95 288.95,128.95 289.65,128.95 290.35,128.95 286.15,129.65 286.85,129.65 287.55,129.65 288.25,129.65 288.95,129.65 289.65,129.65 290.35,129.65 286.15,130.35 286.85,130.35 287.55,130.35 288.25,130.35 288.95,130.35 289.65,130.35 290.35,130.35 286.15,131.05 286.85,131.05 287.55,131.05 288.25,131.05 288.95,131.05 289.65,131.05 290.35,131.05 286.15,131.75 286.85,131.75 287.55,131.75 288.25,131.75 288.95,131.75 289.65,131.75 290.35,131.75 284.05,132.15 284.85,132.15 286.15,132.45 286.85,132.45 287.55,132.45 288.25,132.45 288.95,132.45 289.65,132.45 290.35,132.45 268,138.9 264.15,142 264.85,142 270.45,142 271.15,142 281.5,142.6 286.05,147.85 286.75,147.85 286.05,148.55 286.75,148.55 286.05,149.25 286.75,149.25 287.45,149.25 288.15,149.25 286.05,149.95 286.75,149.95 287.45,149.95 288.15,149.95 284.075,150.05 284.875,150.05 286.05,150.65 286.75,150.65 287.45,150.65 288.15,150.65 303.6,151 310.6,151 312,151 313.4,151 314.8,151 316.2,151 323.2,151 324.6,151 286.05,151.35 286.75,151.35 287.45,151.35 288.15,151.35 304.3,151.7 309.9,151.7 311.3,151.7 312.7,151.7 314.1,151.7 315.5,151.7 316.9,151.7 322.5,151.7 323.9,151.7 286.05,152.05 286.75,152.05 287.45,152.05 288.15,152.05 303.6,152.4 305,152.4 306.4,152.4 307.8,152.4 309.2,152.4 310.6,152.4 312,152.4 313.4,152.4 314.8,152.4 316.2,152.4 317.6,152.4 319,152.4 320.4,152.4 321.8,152.4 323.2,152.4 324.6,152.4 304.3,153.1 305.7,153.1 307.1,153.1 308.5,153.1 309.9,153.1 311.3,153.1 312.7,153.1 314.1,153.1 315.5,153.1 316.9,153.1 318.3,153.1 321.1,153.1 322.5,153.1 323.9,153.1
OUTA1: IC304.14 R104.2 | length 178.1
  TOP w0.3: R104.2@162.35,127.797 162.35,127.2 163.35,126.2 v1(165.6,126.2)
  TOP w0.45: R104.2@162.35,127.797 R104.2@162.35,127.975
  Mid-Layer 2 w0.3: v1(165.6,126.2) 163.6,126.2 158.7,121.3 158.7,105.4 164.85,99.25 168.95,99.25 178.15,90.05 190.05,90.05 190.45,89.65 194.1,89.65 196.1,87.65 196.1,86.35 209.6,72.85 209.6,28.1 v1(213.8,23.9)
  BOTTOM w0.3: v1(213.8,23.9) 215.05,22.65 235.9,22.65 242.205,28.955 IC304.14@243.057,28.955
  BOTTOM w0.55: IC304.14@243.057,28.955 IC304.14@243.68,28.955
OUTA2: DP251.1 IC251.22 pad.@264.3,27.4 R355.2 | length 17.4
  TOP w0.3: pad.@264.3,27.4 264.8,26.9 DP251.1@266.95,26.9
  BOTTOM w0.3: R355.2@261.403,27.4 pad.@264.3,27.4 264.661,27.4 266.936,29.675 IC251.22@274.076,29.675
  BOTTOM w0.4: IC251.22@274.076,29.675 IC251.22@274.837,29.675
  BOTTOM w0.45: R355.2@261.225,27.4 R355.2@261.403,27.4
OUTB1: IC304.13 R103.2 | length 179.3
  TOP w0.3: v1(165.6,127.15) R103.2@165.6,127.947
  TOP w0.45: R103.2@165.6,127.947 R103.2@165.6,127.975
  Mid-Layer 2 w0.3: v1(165.6,127.15) 165.6,127.9 164.95,128.55 163.6,128.55 157.85,122.8 157.85,105.1 164.6,98.35 169,98.35 177.9,89.45 189.45,89.45 190.1,88.8 193.95,88.8 195,87.75 195,86.3 208.7,72.6 208.7,27.8 v1(212.65,23.85)
  BOTTOM w0.3: v1(212.65,23.85) 214.45,22.05 236.35,22.05 241.985,27.685 IC304.13@242.919,27.685
  BOTTOM w0.55: IC304.13@242.919,27.685 IC304.13@243.68,27.685
OUTB2: DP252.1 IC251.21 pad.@276.4,29.5 R358.2 | length 31.9
  TOP w0.3: pad.@276.4,29.5 277.25,29.5 279.95,32.2 279.95,34.05 283.3,37.4 DP252.1@283.3,40.912
  TOP w2.1: DP252.1@283.3,40.912 DP252.1@283.3,41.4
  BOTTOM w0.3: R358.2@261.403,25.9 264.08,25.9 267.205,29.025 IC251.21@274.076,29.025 ; IC251.21@275.43,29.025 275.925,29.025 pad.@276.4,29.5
  BOTTOM w0.4: IC251.21@274.076,29.025 IC251.21@274.837,29.025 IC251.21@275.43,29.025
  BOTTOM w0.45: R358.2@261.225,25.9 R358.2@261.403,25.9
OUTC1: IC304.12 R115.2 | length 117.6
  TOP w0.3: R115.2@182.95,86.973 182.95,86.2 184.15,85 189.7,85 v1(189.95,85.25)
  TOP w0.45: R115.2@182.95,86.973 R115.2@182.95,87.025
  Mid-Layer 2 w0.3: v1(189.95,85.25) 190.25,84.95 193.6,84.95 203.55,75 203.55,74.25 204.5,73.3 205.25,73.3 207.15,71.4 207.15,26.1 v1(210.15,23.1)
  BOTTOM w0.3: v1(210.15,23.1) 212,23.1 213.65,21.45 236.8,21.45 241.765,26.415 IC304.12@242.861,26.415
  BOTTOM w0.55: IC304.12@242.861,26.415 IC304.12@243.68,26.415
OUTC2: DP253.1 IC251.20 pad.@276.4,28.35 R361.2 | length 32.4
  TOP w0.3: pad.@276.4,28.35 277.35,28.35 280.9,31.9 280.9,33.15 284.25,36.5 DP253.1@286.213,36.5
  TOP w2.1: DP253.1@286.213,36.5 DP253.1@287.5,36.5
  BOTTOM w0.3: R361.2@261.403,23.45 262.55,23.45 267.475,28.375 IC251.20@274.076,28.375 ; IC251.20@275.43,28.375 pad.@276.375,28.375
  BOTTOM w0.4: IC251.20@274.076,28.375 IC251.20@274.837,28.375 IC251.20@275.43,28.375
  BOTTOM w0.45: R361.2@261.225,23.45 R361.2@261.403,23.45
OUTD1: IC304.11 R114.2 | length 113.9
  TOP w0.3: R114.2@186.478,85.675 186.996,85.675 187.171,85.85 v1(189.2,85.85)
  TOP w0.45: R114.2@186.3,85.675 R114.2@186.478,85.675
  Mid-Layer 2 w0.3: v1(189.2,85.85) 189.75,86.4 193.35,86.4 204.3,75.45 204.3,74.75 205.1,73.95 205.8,73.95 207.9,71.85 207.9,26.95 211.8,23.05 v1(211.8,22.15)
  BOTTOM w0.3: v1(211.8,22.15) 213.1,20.85 237.2,20.85 241.495,25.145 IC304.11@242.861,25.145
  BOTTOM w0.55: IC304.11@242.861,25.145 IC304.11@243.68,25.145
OUTD2: DP254.1 IC251.19 pad.@264.6,24.4 R364.2 | length 21.3
  TOP w0.3: pad.@264.6,24.4 264.6,23.6 265.5,22.7 DP254.1@266.95,22.7
  BOTTOM w0.3: R364.2@259.453,22.3 262.5,22.3 pad.@264.6,24.4 267.925,27.725 IC251.19@274.076,27.725
  BOTTOM w0.4: IC251.19@274.076,27.725 IC251.19@274.837,27.725
  BOTTOM w0.45: R364.2@259.275,22.3 R364.2@259.453,22.3
OUTE: DP255.1 IC251.18 R164.1 R214.1 | length 140.3
  TOP w0.3: v1(290.1,40.7) 290.1,39.75 291.4,38.45 DP255.1@293.05,38.45
  Mid-Layer 3 w0.3: v1(263.45,136.4) 263.45,108.6 266.35,105.7 266.35,102.85 263.45,99.95 v1(263.45,98.55) 263.45,76.8 290.1,50.15 v1(290.1,40.7) 290.1,39.65 286.6,36.15 285.3,36.15 280.2,31.05 280.2,29.25 v1(278.15,27.2)
  BOTTOM w0.3: v1(263.45,98.55) 264.35,99.45 R214.1@264.923,99.45 ; v1(263.45,136.4) 263.45,137.05 263.95,137.55 R164.1@264.747,137.55 ; IC251.18@275.43,27.075 276.175,27.075 276.3,27.2 v1(278.15,27.2)
  BOTTOM w0.4: IC251.18@274.837,27.075 IC251.18@275.43,27.075
  BOTTOM w0.45: R164.1@264.747,137.55 R164.1@264.925,137.55 ; R214.1@264.923,99.45 R214.1@264.925,99.45
OUTF: DP256.1 IC251.17 R165.1 R215.1 | length 146.9
  TOP w0.3: v1(288.95,42.05) 288.95,43.681 289.869,44.6 DP256.1@293.05,44.6
  Mid-Layer 3 w0.3: v1(262.55,137.35) 262.55,108.2 265.75,105 265.75,103.35 262.55,100.15 v1(262.55,99.25) 262.55,76.4 288.95,50 v1(288.95,42.05) 288.95,39.5 286.25,36.8 285,36.8 279.55,31.35 279.55,29.95 276.55,26.95 v1(276.55,26.425)
  BOTTOM w0.3: v1(262.55,99.25) 262.55,100.6 264.1,102.15 R215.1@264.747,102.15 ; v1(262.55,137.35) 262.55,138.7 264.1,140.25 R165.1@264.747,140.25 ; IC251.17@275.599,26.425 v1(276.55,26.425)
  BOTTOM w0.4: IC251.17@274.837,26.425 IC251.17@275.599,26.425
  BOTTOM w0.45: R215.1@264.747,102.15 R215.1@264.925,102.15 ; R165.1@264.747,140.25 R165.1@264.925,140.25
P48V: C510.2 C511.2 C512.2 CN501.1 CN501.2 CN501.3 CN501.4 CN501.5 CN501.6 CN501.7 CN501.8 CN503.1 IC501.4 Q501.5 Q501.6 Q501.7 Q501.8 Q502.5 Q502.6 Q502.7 Q502.8 Q503.5 Q503.6 Q503.7 Q503.8 Q504.5 Q504.6 Q504.7 Q504.8 | length 44.3
  Mid-Layer 2 w0.3: CN503.1@308.3,46.5 309.35,47.55 312.18,50.38 CN501.3@322.29,50.38
  Mid-Layer 3 w0.5: v1(321.45,29) 319.15,31.3 319.15,44.7 CN501.4@322.29,47.84
  BOTTOM w0.5: 332.35,45.25 C510.2@333.9,45.25 ; 333.9,46.45 C510.2@333.9,45.25 ; 336.4,46.25 C511.2@336.4,45.25 ; 337.75,45.25 C511.2@336.4,45.25 ; C510.2@333.9,45.25 C511.2@336.4,45.25
PFC_OFF: C66.2 DP61.1 IC52.18 R308.1 | length 2.2
  BOTTOM w0.3: R308.1@156.713,31.9 DP61.1@158.7,31.9
  BOTTOM w0.45: R308.1@156.525,31.9 R308.1@156.713,31.9
PFC_OUT: C51.2 C52.2 C78.2 C79.2 D55.1 D56.C D57.C DP51.1 F401.1 R92.2 R101.2 R309.1 T101.2 | length 31.5
  TOP w0.3: DP51.1@193.5,22.6 v1(193.5,25.75)
  Mid-Layer 2 w0.3: C52.2@184.7,50.5 193.5,41.7 v1(193.5,25.75)
PN: C11.1 C51.1 C52.1 C53.1 C54.1 C55.1 C56.1 C57.1 C58.1 C59.1 C60.1 C61.1 C62.1 C63.1 C64.1 C65.1 C66.1 C67.1 C68.1 C69.1 C70.1 C71.1 C73.1 C75.1 C77.1 C78.1 C79.1 C81.1 C82.1 C101.1 C102.1 C103.1 C104.1 C105.1 C106.1 C107.1 C110.1 C111.1 C112.1 C113.1 C114.1 C115.1 C116.1 C117.1 C118.1 C121.1 C301.1 C302.1 C303.1 C304.1 C305.1 C306.1 C307.1 C308.1 C309.1 C310.1 C311.1 C401.1 C405.1 C407.1 C408.1 C409.1 C410.1 C411.1 C412.1 C413.1 C414.1 D55.4 D68.A D107.A D109.A D116.A D302.A DP1.1 DP59.1 DP304.1 HS1.1 HS2.1 IC51.3 IC52.16 IC101.4 IC101.5 IC101.9 IC102.4 IC102.5 IC102.9 IC301.2 IC302.2 IC304.9 IC304.15 IC401.4 IC403.2 pad.@173.6,137.1 pad.@173.6,137.8 pad.@194.4,94.1 pad.@194.4,94.8 Q1.S Q51.S Q52.S Q102.S Q104.S Q301.S Q302.S Q303.S R5.1 R6.1 R52.1 R56.1 R60.1 R64.1 R74.1 R76.1 R78.1 R79.1 R80.1 R82.1 R84.1 R88.1 R89.1 R90.1 R91.1 R96.1 R102.1 R105.2 R113.1 R116.2 R124.1 R306.1 R312.1 R315.1 R317.1 R319.1 R321.1 R323.1 R404.1 R405.1 R406.1 R411.1 R412.1 R414.1 R418.1 R419.1 R420.1 R421.1 R422.1 R423.1 T51.2 T52.2 T401.4 | length 618.5
  TOP w0.3: v1(100.7,147.2) R422.1@100.7,148.497 ; Q51.S@137.46,80.7 137.46,72 139.56,69.9 C82.1@142.797,69.9 ; R321.1@142.3,28.825 142.916,29.441 cw(c143.058,29.3) 143.058,29.5 v1(144.5,29.5) v1(145.5,29.5) v1(146.5,29.5) v1(147.5,29.5) ; R56.1@142.975,68.978 C82.1@142.975,69.722 ; v1(151.15,67.7) C59.1@151.95,67.7 ; Q52.S@168.66,80.7 168.66,75.365 168.975,75.05 C81.1@171.887,75.05 ; v1(169.8,21.9) 170.8,22.9 R82.1@170.8,23.497 ; R64.1@172.075,74.128 C81.1@172.075,74.872 ; R113.1@178.075,146.478 C110.1@178.075,147.222 ; C110.1@178.253,147.4 178.84,147.4 Q102.S@183.24,151.8 ; v1(181.2,67.15) 181.775,67.15 182.025,67.4 C61.1@182.025,68.322 ; C113.1@181.85,86.873 181.85,86.35 183.85,84.35 190.5,84.35 190.95,84.8 v1(190.95,85.65) ; C413.1@205.175,81.75 205.4,81.525 IC403.2@205.4,78.527 ; C412.1@205.225,76.04 205.225,76.4 205.4,76.575 IC403.2@205.4,77.32 ; v1(205.25,75.05) C412.1@205.25,75.875
  TOP w0.4: C412.1@205.25,75.875 C412.1@205.25,76
  TOP w0.45: R422.1@100.7,148.497 R422.1@100.7,148.675 ; C82.1@142.797,69.9 C82.1@142.975,69.9 C82.1@142.975,69.722 ; R56.1@142.975,68.8 R56.1@142.975,68.978 ; C59.1@151.95,67.7 C59.1@152.075,67.7 ; R82.1@170.8,23.497 R82.1@170.8,23.675 ; C81.1@171.887,75.05 C81.1@172.075,75.05 C81.1@172.075,74.872 ; R64.1@172.075,73.95 R64.1@172.075,74.128 ; R113.1@178.075,146.3 R113.1@178.075,146.478 ; C110.1@178.075,147.222 C110.1@178.075,147.4 C110.1@178.253,147.4 ; C113.1@181.85,86.873 C113.1@181.85,87.025 ; C61.1@182.025,68.322 C61.1@182.025,68.5 ; C412.1@205.225,75.95 C412.1@205.225,76.04
  TOP w0.5: C408.1@227.006,64.025 230.25,64.025 233.85,60.425 233.85,44.9 235.3,43.45 T401.4@238.5,43.45
  TOP w0.55: IC403.2@205.4,77.32 IC403.2@205.4,77.825 IC403.2@205.4,78.527
  TOP w1.6: C408.1@226.55,64.025 C408.1@227.006,64.025
  Mid-Layer 1 w0.3: v1(112.15,85.45) 114.641,82.959 ccw(c114.783,83.1) 114.783,82.9 v1(115.35,82.9)
  Mid-Layer 1 w0.5: 156.4,21.15 DP59.1@156.4,22.7 ; 156.4,24.3 DP59.1@156.4,22.7 ; 158.05,22.7 DP59.1@156.4,22.7 ; 210.75,41.45 C401.1@213.1,41.45 ; 213.1,39.45 C401.1@213.1,41.45 ; 213.1,43.15 C401.1@213.1,41.45 ; 215.45,41.45 C401.1@213.1,41.45
  Mid-Layer 1 w1: T401.4@238.5,43.45 240.85,41.1 240.85,34.55 238.4,32.1 238.4,30.9 C414.1@239.4,29.9
  Mid-Layer 1 w1.5: 135.21,80.7 Q51.S@137.46,80.7 ; 137.46,78.45 Q51.S@137.46,80.7 ; 137.46,82.95 Q51.S@137.46,80.7 ; 138.7,80.7 Q51.S@137.46,80.7 ; 139.545,151.65 D55.4@141.9,151.65 ; 141.9,149.295 D55.4@141.9,151.65 ; 141.9,153.066 D55.4@141.9,151.65 ; 144.255,151.65 D55.4@141.9,151.65 ; 145.06,40.7 C51.1@148.9,40.7 ; 148.9,36.86 C51.1@148.9,40.7 ; 148.9,43.95 C51.1@148.9,40.7 ; 152.74,40.7 C51.1@148.9,40.7 ; 166.41,80.7 Q52.S@168.66,80.7 ; 168.66,78.45 Q52.S@168.66,80.7 ; 168.66,82.95 Q52.S@168.66,80.7 ; 169.95,80.7 Q52.S@168.66,80.7 ; 180.86,40.5 C52.1@184.7,40.5 ; 184.7,36.75 C52.1@184.7,40.5 ; 184.7,43.7 C52.1@184.7,40.5 ; 185.232,25 DP1.1@186.7,25 ; 186.7,23.686 DP1.1@186.7,25 ; 186.7,27.15 DP1.1@186.7,25 ; 188.315,25 DP1.1@186.7,25 ; 188.54,40.5 C52.1@184.7,40.5 ; 198.311,141.7 D109.A@200.5,141.7 200.5,139.65 ; 200.39,135.2 HS2.1@203.04,135.2 ; 200.44,124 HS1.1@203.04,124 ; 203.04,122.15 HS1.1@203.04,124 ; 203.04,126.6 HS1.1@203.04,124 ; 203.04,132.55 HS2.1@203.04,135.2 ; 203.04,137.85 HS2.1@203.04,135.2 ; 205.162,124 HS1.1@203.04,124
  Mid-Layer 2 w0.3: v1(133.1,101.9) 133.1,98.95 131.85,97.7 131.85,70 141,60.85 156.95,60.85 161.8,56 170.3,56 171.75,54.55 171.75,29.3 173.1,27.95 173.1,23.05 v1(173.6,22.55) ; v1(150,104.8) 150.85,103.95 153.45,103.95 158.55,98.85 158.55,88 163.75,82.8 163.75,76.5 169.15,71.1 169.15,61.55 176.9,53.8 176.9,27.25 175.4,25.75 175.15,25.75 v1(174.6,26.3) ; v1(217.3,36.9) 217.3,32.4 221.55,28.15 228.35,28.15 v1(229.35,29.15)
  Mid-Layer 4 w0.3: v1(112.15,85.45) 114.641,82.959 ccw(c114.783,83.1) 114.783,82.9 v1(115.35,82.9)
  Mid-Layer 4 w0.5: 156.4,21.15 DP59.1@156.4,22.7 ; 156.4,24.3 DP59.1@156.4,22.7 ; 158.05,22.7 DP59.1@156.4,22.7 ; 210.75,41.45 C401.1@213.1,41.45 ; 213.1,39.45 C401.1@213.1,41.45 ; 213.1,43.15 C401.1@213.1,41.45 ; 215.45,41.45 C401.1@213.1,41.45
  Mid-Layer 4 w1: T401.4@238.5,43.45 240.85,41.1 240.85,34.55 238.4,32.1 238.4,30.9 C414.1@239.4,29.9
  Mid-Layer 4 w1.5: 135.21,80.7 Q51.S@137.46,80.7 ; 137.46,78.45 Q51.S@137.46,80.7 ; 137.46,82.95 Q51.S@137.46,80.7 ; 138.7,80.7 Q51.S@137.46,80.7 ; 139.545,151.65 D55.4@141.9,151.65 ; 141.9,149.295 D55.4@141.9,151.65 ; 141.9,153.066 D55.4@141.9,151.65 ; 144.255,151.65 D55.4@141.9,151.65 ; 145.06,40.7 C51.1@148.9,40.7 ; 148.9,36.86 C51.1@148.9,40.7 ; 148.9,43.95 C51.1@148.9,40.7 ; 152.74,40.7 C51.1@148.9,40.7 ; 166.41,80.7 Q52.S@168.66,80.7 ; 168.66,78.45 Q52.S@168.66,80.7 ; 168.66,82.95 Q52.S@168.66,80.7 ; 169.95,80.7 Q52.S@168.66,80.7 ; 180.86,40.5 C52.1@184.7,40.5 ; 184.7,36.75 C52.1@184.7,40.5 ; 184.7,43.7 C52.1@184.7,40.5 ; 185.232,25 DP1.1@186.7,25 ; 186.7,23.686 DP1.1@186.7,25 ; 186.7,27.15 DP1.1@186.7,25 ; 188.315,25 DP1.1@186.7,25 ; 188.54,40.5 C52.1@184.7,40.5 ; 198.311,141.7 D109.A@200.5,141.7 200.5,139.65 ; 200.39,135.2 HS2.1@203.04,135.2 ; 200.44,124 HS1.1@203.04,124 ; 203.04,122.15 HS1.1@203.04,124 ; 203.04,126.6 HS1.1@203.04,124 ; 203.04,132.55 HS2.1@203.04,135.2 ; 203.04,137.85 HS2.1@203.04,135.2 ; 205.162,124 HS1.1@203.04,124
  BOTTOM w0.3: v1(115.35,82.9) C11.1@116.275,82.9 ; R52.1@132.647,103.086 132.647,102.353 v1(133.1,101.9) 133.1,100.875 ; C58.1@133.675,100.3 133.1,100.875 ; T51.2@135.9,88.1 134.1,88.1 133.1,89.1 133.1,100.875 ; R60.1@149.137,106.347 149.137,105.662 v1(150,104.8) 150,104.175 C60.1@150.675,103.5 ; C60.1@150.675,103.46 150.675,102.725 151.1,102.3 152.65,102.3 159.2,95.75 159.2,90.5 T52.2@161.6,88.1 ; v1(157.85,93.9) R420.1@157.85,95.4 ; C67.1@159.9,29.45 161.05,29.45 161.3,29.2 C68.1@161.3,28.625 ; C66.1@161.378,34.325 R84.1@162.222,34.325 ; C68.1@161.478,28.625 162.3,28.625 162.5,28.425 IC52.16@163.276,28.425 ; R84.1@162.578,34.325 R78.1@163.722,34.325 ; C121.1@189.825,110.303 R124.1@189.825,111.047
  BOTTOM w0.4: R420.1@157.85,95.4 R420.1@157.85,95.575 ; IC52.16@163.276,28.425 IC52.16@163.975,28.425
  BOTTOM w0.45: C60.1@150.675,103.46 C60.1@150.675,103.5 ; C66.1@161.2,34.325 C66.1@161.378,34.325 ; C68.1@161.3,28.625 C68.1@161.478,28.625 ; R84.1@162.222,34.325 R84.1@162.4,34.325 R84.1@162.578,34.325 ; R78.1@163.722,34.325 R78.1@163.9,34.325 ; C121.1@189.825,110.125 C121.1@189.825,110.303 ; R124.1@189.825,111.047 R124.1@189.825,111.225
  BOTTOM w0.5: C405.1@227.95,36.96 227.95,37.6 228.45,38.1 233.15,38.1 T401.4@238.5,43.45
  BOTTOM w0.8: C405.1@227.95,36.55 C405.1@227.95,36.96
  BOTTOM w0.895: R52.1@132.647,103.086 R52.1@132.647,104.2 ; R60.1@149.137,106.347 R60.1@149.137,107.2
  BOTTOM w1.1: C67.1@159.6,29.45 C67.1@159.9,29.45
  other v1: 241.45,21.8 242.15,21.8 165.8,21.9 167.8,21.9 160.65,22.75 231,24.6 152.9,24.65 231,25.3 175.35,26.95 165.4,28.4 166.2,28.4 154.8,29.8 155.6,29.8 241.15,29.8 174,31.25 174,32.05 174,32.85 164.8,34.45 165.6,34.45 169.5,59.6 205.45,66.95 205.45,67.75 165.55,68.1 166.35,68.1 199.5,74.9 191.65,85.65 197.65,85.8 197.65,86.5 198.55,95.35 198.55,96.05 169.25,125.5 169.95,125.5 170.65,125.5 164.55,127.15 169.25,128.65 169.95,128.65 170.65,128.65 175.5,136.35 176.2,136.35
RY_OFF: C311.2 D303.C D304.C IC301.4 Q302.G R4.2 R7.1 | length 73.9
  Mid-Layer 3 w0.3: v1(116.25,85.3) 117.567,85.3 cw(c117.567,85.1) 117.708,85.242 122.691,80.259 cw(c122.55,80.117) 122.75,80.117 122.75,72.333 ccw(c122.95,72.333) 122.809,72.191 133.441,61.559 cw(c133.3,61.417) 133.5,61.417 133.5,52.783 ccw(c133.7,52.783) 133.559,52.641 143.791,42.409 cw(c143.65,42.267) 143.85,42.267 143.85,36.033 ccw(c144.05,36.033) 143.908,35.892 150.891,28.909 cw(c150.75,28.767) 150.95,28.767 v1(150.95,26.5)
SIG1: C1.2 C2.2 F1.2 L1.1 R1.2 RV1.1 | length 19.6
  BOTTOM w0.3: L1.1@62.643,46.97 65.477,49.804 cw(c65.618,49.662) 65.618,49.862 R1.2@68.049,49.863
  BOTTOM w0.5: F1.2@57.05,72.45 57.05,75.45 62.3,80.7 C2.2@63.7,80.7
  BOTTOM w0.895: R1.2@68.049,49.863 R1.2@69.2,49.863
SIG2: C1.1 C3.2 CN1.3 CN2.3 L1.4 R2.1 RV1.2 | length 77.5
  Mid-Layer 2 w0.5: CN2.3@42.58,25.7 42.58,41.37 40.5,43.45 CN1.3@40.5,54.1 54.75,54.1 RV1.2@65.15,64.5
  BOTTOM w0.3: L1.4@62.643,36.97 66.617,32.996 ccw(c66.758,33.138) 66.758,32.938 R2.1@68.249,32.938
  BOTTOM w0.5: C3.2@63.7,74.8 65.15,73.35 RV1.2@65.15,64.5
  BOTTOM w0.895: R2.1@68.249,32.938 R2.1@69.4,32.938
SIG6: C8.2 C9.1 D52.A D54.A D55.3 L2.3 L52.1 | length 26.4
  BOTTOM w0.3: D54.A@120.806,31 118.172,33.634 cw(c118.313,33.776) 118.113,33.776 L2.3@118.113,36.97 120.856,38.17 ; 120.857,38.17 ccw(c120.776,38.353) 120.917,38.211 ; 120.917,38.211 D52.A@123.106,40.4
  BOTTOM w0.5: C8.2@82.2,95.4 84.3,97.5 C9.1@94.5,97.5
SIG8: C9.2 D51.A D53.A D55.2 L51.1 R3.2 RY1.2 | length 130.3
  Mid-Layer 2 w5: L51.1@100.6,123.2 126.7,149.3 126.7,151.65
  Mid-Layer 3 w0.3: RY1.2@109.7,72.05 109.7,60.863 ccw(c109.9,60.863) 109.759,60.721 112.981,57.499 ccw(c113.123,57.64) 113.123,57.44 119.197,57.44 cw(c119.197,57.24) 119.339,57.381 128.821,47.899 cw(c128.68,47.757) 128.88,47.757 v1(128.88,34.7)
  Mid-Layer 3 w5: L51.1@100.6,123.2 126.7,149.3 126.7,151.65
  BOTTOM w0.3: v1(128.88,34.7) 129.241,35.061 ccw(c129.1,35.203) 129.3,35.203 D51.A@129.3,37.406
SIG9: IC1.2 IC1.3 R1.1
SIG10: IC1.6 IC1.7 R2.2
SIG11: D57.A L52.2 T52.4 | length 42.3
  BOTTOM w3.5: L52.2@150.5,129.1 150.5,118.95 159.65,109.8 159.65,103.7 162.75,100.6 163.8,100.6 168.6,95.8 T52.4@168.6,94.875
SIG12: D56.A L51.2 T51.4
SIG0012: C7.2 L2.2 R3.1 RY1.3 | length 35.4
  Mid-Layer 2 w0.3: 99.4,79.2 101.526,77.074 cw(c101.385,76.933) 101.585,76.933 R3.1@101.585,66.152
  Mid-Layer 2 w0.5: C7.2@82.2,89.5 89.1,89.5 99.4,79.2
SIG0013: D1.A Q1.D R6.2 RY1.1 | length 13.4
  BOTTOM w0.3: R6.2@110.375,85.4 109.759,86.016 cw(c109.9,86.158) 109.7,86.158 RY1.1@109.7,88.55 ; D1.A@112.144,92.55 111.383,92.55 ccw(c111.383,92.35) 111.241,92.491 109.759,91.009 ccw(c109.9,90.867) 109.7,90.867 RY1.1@109.7,88.55 ; Q1.D@113.6,87.75 112.859,88.491 ccw(c112.717,88.35) 112.717,88.55 RY1.1@109.7,88.55
  BOTTOM w0.4: D1.A@112.144,92.55 D1.A@112.4,92.55
SIG0014: Q1.G R5.2 R7.2
SIG15: D63.A R61.2 T52.1 | length 13.4
  BOTTOM w0.3: R61.2@153.725,103.5 153.725,103.175 T52.1@161.6,95.3 ; R61.2@153.725,103.678 D63.A@153.725,104.845
  BOTTOM w0.45: R61.2@153.725,103.5 R61.2@153.725,103.678
  BOTTOM w0.5: D63.A@153.725,104.845 D63.A@153.725,105.475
